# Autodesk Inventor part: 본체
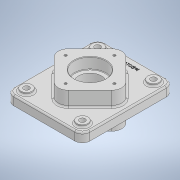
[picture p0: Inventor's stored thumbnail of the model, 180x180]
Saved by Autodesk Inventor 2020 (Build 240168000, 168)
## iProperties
Created: 2021-07
Part Number: 본체
Material: 일반
Document SubType Name: Modeling
Designer: Owner
Density: 1 g/cm^3
Appearance: 기본값
Mass: 807.976 g
Surface Area: 961.758 cm^2
Volume: 807.976 cm^3
Author: Owner
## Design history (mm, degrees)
sketch "스케치1"
  geometry: L1 (75, -90)-(-75, -90); L2 (-75, -90)-(-75, 90); L3 (-75, 90)-(75, 90); L4 (75, 90)-(75, -90); L5 (75, -90)-(-75, 90); L6 (-75, -90)-(75, 90); 1 further point
  constraints: 12 end point, 2 midpoint, 2 parallel, 1 horizontal, 1 perpendicular
  dimensions: "d0" = 150 distance of L2.end L3.end; "d1" = 180 distance of L1.end L2.end
extrude "돌출1" new body sketch "스케치1" distance "d2" = 18; taper "d3" = 0 deg
sketch "스케치2"
  geometry: L1 (14.142, 56.569)-(56.569, 14.142); L2 (56.569, -14.142)-(14.142, -56.569); L3 (-14.142, -56.569)-(-56.569, -14.142); L4 (-56.569, 14.142)-(-14.142, 56.569); L5 (0, 70.711)-(0, -70.711); L6 (70.711, 0)-(-70.711, 0); A1 r 20 centre (-42.426, 0) between (-56.569, 14.142) and (-56.569, -14.142); A2 r 20 centre (0, 42.426) between (14.142, 56.569) and (-14.142, 56.569); A3 r 20 centre (42.426, 0) between (56.569, -14.142) and (56.569, 14.142); A4 r 20 centre (0, -42.426) between (-14.142, -56.569) and (14.142, -56.569); 3 further points
  constraints: 12 end point, 8 point on circle, 8 point on line, 8 tangent, 4 centre point, 4 midpoint, 3 equal radius, 2 parallel, 1 horizontal alignment, 1 perpendicular, 1 vertical alignment
  dimensions: "d4" = 100 distance between parallel lines of L2 L4; "d5" = 20 radius of A1
extrude "돌출2" join sketch "스케치2" distance "d6" = 29; taper "d7" = 0 deg
sketch "스케치3"
  geometry: L1 (56.569, 14.142)-(14.142, 56.569); L2 (-14.142, 56.569)-(-56.569, 14.142); L3 (-56.569, -14.142)-(-14.142, -56.569); L4 (14.142, -56.569)-(56.569, -14.142); L5 (70.711, 0)-(-70.711, 0); L6 (0, 70.711)-(0, -70.711); A1 r 20 centre (42.426, 0) between (56.569, -14.142) and (56.569, 14.142); A2 r 20 centre (0, -42.426) between (-14.142, -56.569) and (14.142, -56.569); A3 r 20 centre (-42.426, 0) between (-56.569, 14.142) and (-56.569, -14.142); A4 r 20 centre (0, 42.426) between (14.142, 56.569) and (-14.142, 56.569); 2 further points
  constraints: 12 end point, 8 point on circle, 8 point on line, 8 tangent, 4 centre point, 3 equal radius, 3 midpoint, 2 parallel, 1 horizontal alignment, 1 perpendicular, 1 vertical alignment
  dimensions: "d8" = 100 distance of L5.end L6.start; "d9" = 20 radius of A1 (derived)
extrude "돌출3" join sketch "스케치3" distance "d10" = 23; taper "d11" = 0 deg
sketch "스케치4"
  geometry: C1 r 31 at (0, 0); 1 further point
  constraints: 1 centre point, 1 coincident
  dimensions: "d12" = 62 diameter of C1
extrude "돌출4" cut sketch "스케치4" distance "d13" = 22; taper "d14" = 0 deg
sketch "스케치5"
  geometry: C1 r 31 at (0, 0); 1 further point
  constraints: 1 centre point, 1 coincident
  dimensions: "d15" = 62 diameter of C1
extrude "돌출5" cut sketch "스케치5" distance "d16" = 22; taper "d17" = 0 deg
sketch "스케치6"
  geometry: C1 r 22.5 at (0, 0); 1 further point
  constraints: 1 centre point, 1 coincident
  dimensions: "d18" = 45 diameter of C1
extrude "돌출6" cut sketch "스케치6" stored distance "d19" = 22; taper "d20" = 0 deg
sketch "스케치7"
  geometry: C1 r 31 at (0, 0) reference; A1 r 48 centre (0, 0) between (0, 48) and (0, 48); 5 further points
  constraints: 6 point on circle, 4 vertical alignment, 2 horizontal alignment, 1 centre point, 1 coincident
  dimensions: "d21" = 96 diameter of A1
hole "구멍1" sketch "스케치7" at (0, 48), (0, -48), (-48, 0), (48, 0) diameter "d22" = 4.917; stored, may be unused: countersink angle "d26" = 90 deg, drill point angle "d28" = 118 deg; dims "d23" = 10, "d24" = 4, "d25" = 2, "d27" = 13
sketch "스케치8"
  geometry: C1 r 31 at (0, 0) reference; C2 r 48 at (0, 0); C3 r 2.458 at (0, 48) reference; C4 r 2.458 at (48, 0) reference; C5 r 2.458 at (0, -48) reference; C6 r 2.458 at (-48, 0) reference; 5 further points
  constraints: 5 coincident, 1 centre point
  dimensions: "d29" = 96 diameter of C2
hole "구멍2" sketch "스케치8" at (0, 48), (48, 0), (0, -48), (-48, 0) diameter "d30" = 4.917; stored, may be unused: countersink angle "d34" = 90 deg, drill point angle "d36" = 118 deg; dims "d31" = 10, "d32" = 4, "d33" = 2, "d35" = 13
fillet "모깎기1" dims "d37" = 15
sketch "스케치9"
  geometry: C1 r 11 at (55, -70); C2 r 11 at (-55, -70); C3 r 11 at (55, 70); C4 r 11 at (-55, 70); 1 further point
  constraints: 4 centre point, 2 horizontal alignment, 1 vertical alignment
  dimensions: "d38" = 22 diameter of C1; "d39" = 22 diameter of C2; "d40" = 110 distance of C1.centre C2.centre; "d41" = 22 diameter of C3; "d42" = 22 diameter of C4; "d43" = 110 distance of C3.centre C4.centre; "d44" = 140 distance of C2.centre C4.centre; "d45" = 70 vertical distance of point (0, 0) C4.centre (= 0.5 x d44); "d46" = 55 horizontal distance of point (0, 0) C4.centre
extrude "돌출7" join sketch "스케치9" distance "d47" = 5; taper "d48" = 0 deg
sketch "스케치10"
  geometry: C1 r 11 at (0, 0) reference; C2 r 5.5 at (0, 0); C3 r 11 at (110, 0) reference; C4 r 5.5 at (110, 0); C5 r 11 at (110, 140) reference; C6 r 5.5 at (110, 140); C7 r 11 at (0, 140) reference; C8 r 5.5 at (0, 140); 1 further point
  constraints: 4 centre point, 4 coincident
  dimensions: "d49" = 11 diameter of C2; "d50" = 11 diameter of C4; "d51" = 11 diameter of C6; "d52" = 11 diameter of C8
extrude "돌출8" cut sketch "스케치10" stored distance "d53" = 0; taper "d54" = 0 deg
fillet "모깎기2" dims "d55" = 1
chamfer "모따기1" distance "d56" = 1; stored, may be unused: second distance "d57" = 2, angle "d58" = 45 deg
sketch "스케치11"
  geometry: L1 (60, 90)-(-60, 90) reference; 2 further points
  constraints: 1 vertical alignment, 1 other
  dimensions: "d59" = 15 distance from line of point (0, 75) L1
feature "엠보싱1" sketch "스케치11" dims "d0" = 150, "d1" = 180, "d60" = 0.5, "d61" = 0
fillet "모깎기4" dims "d63" = 3
fillet "모깎기5" dims "d64" = 3
node "솔리드1"
feature "A9D066F2-1C7D-4E18-AEED-F7BC21143FA4" dims "d22" = 4.917, "d23" = 10, "d24" = 4, "d25" = 2, "d26" = 90 deg, "d27" = 13, "d28" = 118 deg
